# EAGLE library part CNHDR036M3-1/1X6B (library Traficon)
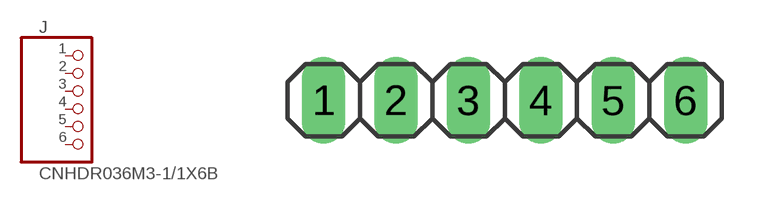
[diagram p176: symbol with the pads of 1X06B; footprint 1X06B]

Designator prefix J

## CNHDR036M3-1/1X6B  [1X06B]
1  TMS  pas
2  TDI  pas
3  TDO  pas
4  TCK  pas
5  GND  pas
6  VCC  pas

## Footprint 1X06B (pad centres in mm)
drill 1.016 long: 1 -6.35,0; 2 -3.81,0; 3 -1.27,0; 4 1.27,0; 5 3.81,0; 6 6.35,0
